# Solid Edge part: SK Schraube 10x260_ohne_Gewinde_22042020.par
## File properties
Author: fknapp
Template: Normal.par
Last saved by: fknapp
Revision: 26
Application: Solid Edge
Username: fknapp
Material: Aluminium
Genauigkeit: 0,99
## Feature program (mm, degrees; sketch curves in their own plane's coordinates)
sketch for "unnamed RevolvedProtrusion 1" plane through (0, 0, 0) normal (0, 0, 1) x-axis (1, 0, 0)
  line (0, 54) -> (9, 54)
  line (9, 54) -> (9, 53)
  line (9, 53) -> (5, 49)
  line (5, 49) -> (5, 46.3)
  line (5, 46.3) -> (4.7548, 46.3)
  arc centre (4.7548, 44.6952) radius 1.6048 from (4.7548, 46.3) to (3.15, 44.6952) ccw
  line (3.15, 44.6952) -> (3.15, 42)
  line (3.15, 42) -> (5, 42)
  line (5, -193) -> (5, 42)
  line (0.5, -206) -> (5, -193)
  line (0, -206) -> (0.5, -206)
revolve "unnamed RevolvedProtrusion 1" add full turn 360 deg about sketch line (0, 54) -> (0, -206)
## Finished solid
Body 1: solid body, 11 faces, 10 edges, 0 vertices.
  Faces by surface: cylinder 4, plane 4, cone 2, torus 1
  Edges by curve: circle 10
Bounding box of the edges (mm; curved faces can reach further): 18.000 x 260.000 x 18.000, from (-9, -206, -9) to (9, 54, 9).
Cylindrical faces by radius (mm): R3.15 x1, R5 x2, R9 x1
Conical faces (half-angle, radius in mm at the cone's reference point): 19.0935 deg R5 x1, 45 deg R9 x1
Toroidal faces (ring radius, tube radius in mm): R4.7548 r1.6048 x1
Planar faces by outward normal: +y 2, -y 2
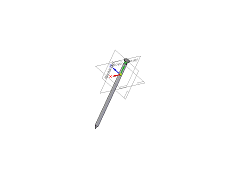
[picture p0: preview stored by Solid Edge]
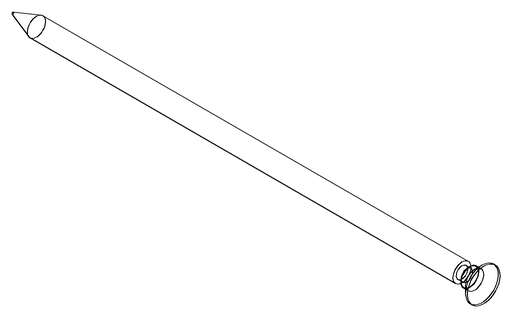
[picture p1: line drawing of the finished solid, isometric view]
